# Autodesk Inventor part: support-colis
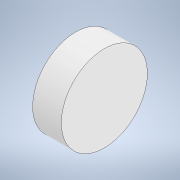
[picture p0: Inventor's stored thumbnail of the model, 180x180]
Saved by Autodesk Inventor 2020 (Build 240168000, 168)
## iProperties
Created: 2021-10
Part Number: support-colis
Material: Générique
Document SubType Name: Modeling
Designer: bruno
Density: 1 g/cm^3
Appearance: Blanche
Author: bruno
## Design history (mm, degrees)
sketch "Esquisse1"
  geometry: C1 r 15 at (0, 0); 1 further point
  constraints: 1 centre point, 1 coincident
  dimensions: "d0" = 30 diameter of C1
extrude "Extrusion1" new body sketch "Esquisse1" distance "d1" = 10; taper "d2" = 0 deg
node "Solide1"
